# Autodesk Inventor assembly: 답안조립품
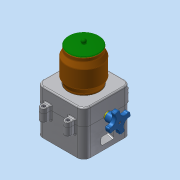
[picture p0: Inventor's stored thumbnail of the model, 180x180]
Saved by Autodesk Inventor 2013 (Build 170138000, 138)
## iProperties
Created: 2018-01
Part Number: 답안조립품
Document SubType Name: Assembly
Designer: dgall
Author: dgall
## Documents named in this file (9)
- C:\Users\dgall\Desktop\480107V1047\답안조립품.iam
- C:\Users\dgall\Desktop\480107V1047\본체.ipt
- C:\Users\dgall\Desktop\480107V1047\핸들축.ipt
- C:\Users\dgall\Desktop\480107V1047\볼트 M3x12.ipt
- C:\Users\dgall\Desktop\480107V1047\핸들.ipt
- C:\Users\dgall\Desktop\480107V1047\본체커버.ipt
- C:\Users\dgall\Desktop\480107V1047\용기.ipt
- C:\Users\dgall\Desktop\480107V1047\용기캡.ipt
- C:\Users\dgall\Desktop\480107V1047\볼트 M4x12.ipt
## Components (2 placed, 2 different names)
1. 핸들축:1
2. 핸들:1
